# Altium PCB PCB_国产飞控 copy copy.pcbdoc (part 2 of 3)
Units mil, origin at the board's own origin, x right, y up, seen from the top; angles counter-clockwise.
Board outline 2782.5 x 2450 mil, 4 copper layers (Top Layer, Inner1, Inner2, Bottom Layer), stack 2.757 mil thick; 92 components, 104 nets, 474 pads, 149 vias.
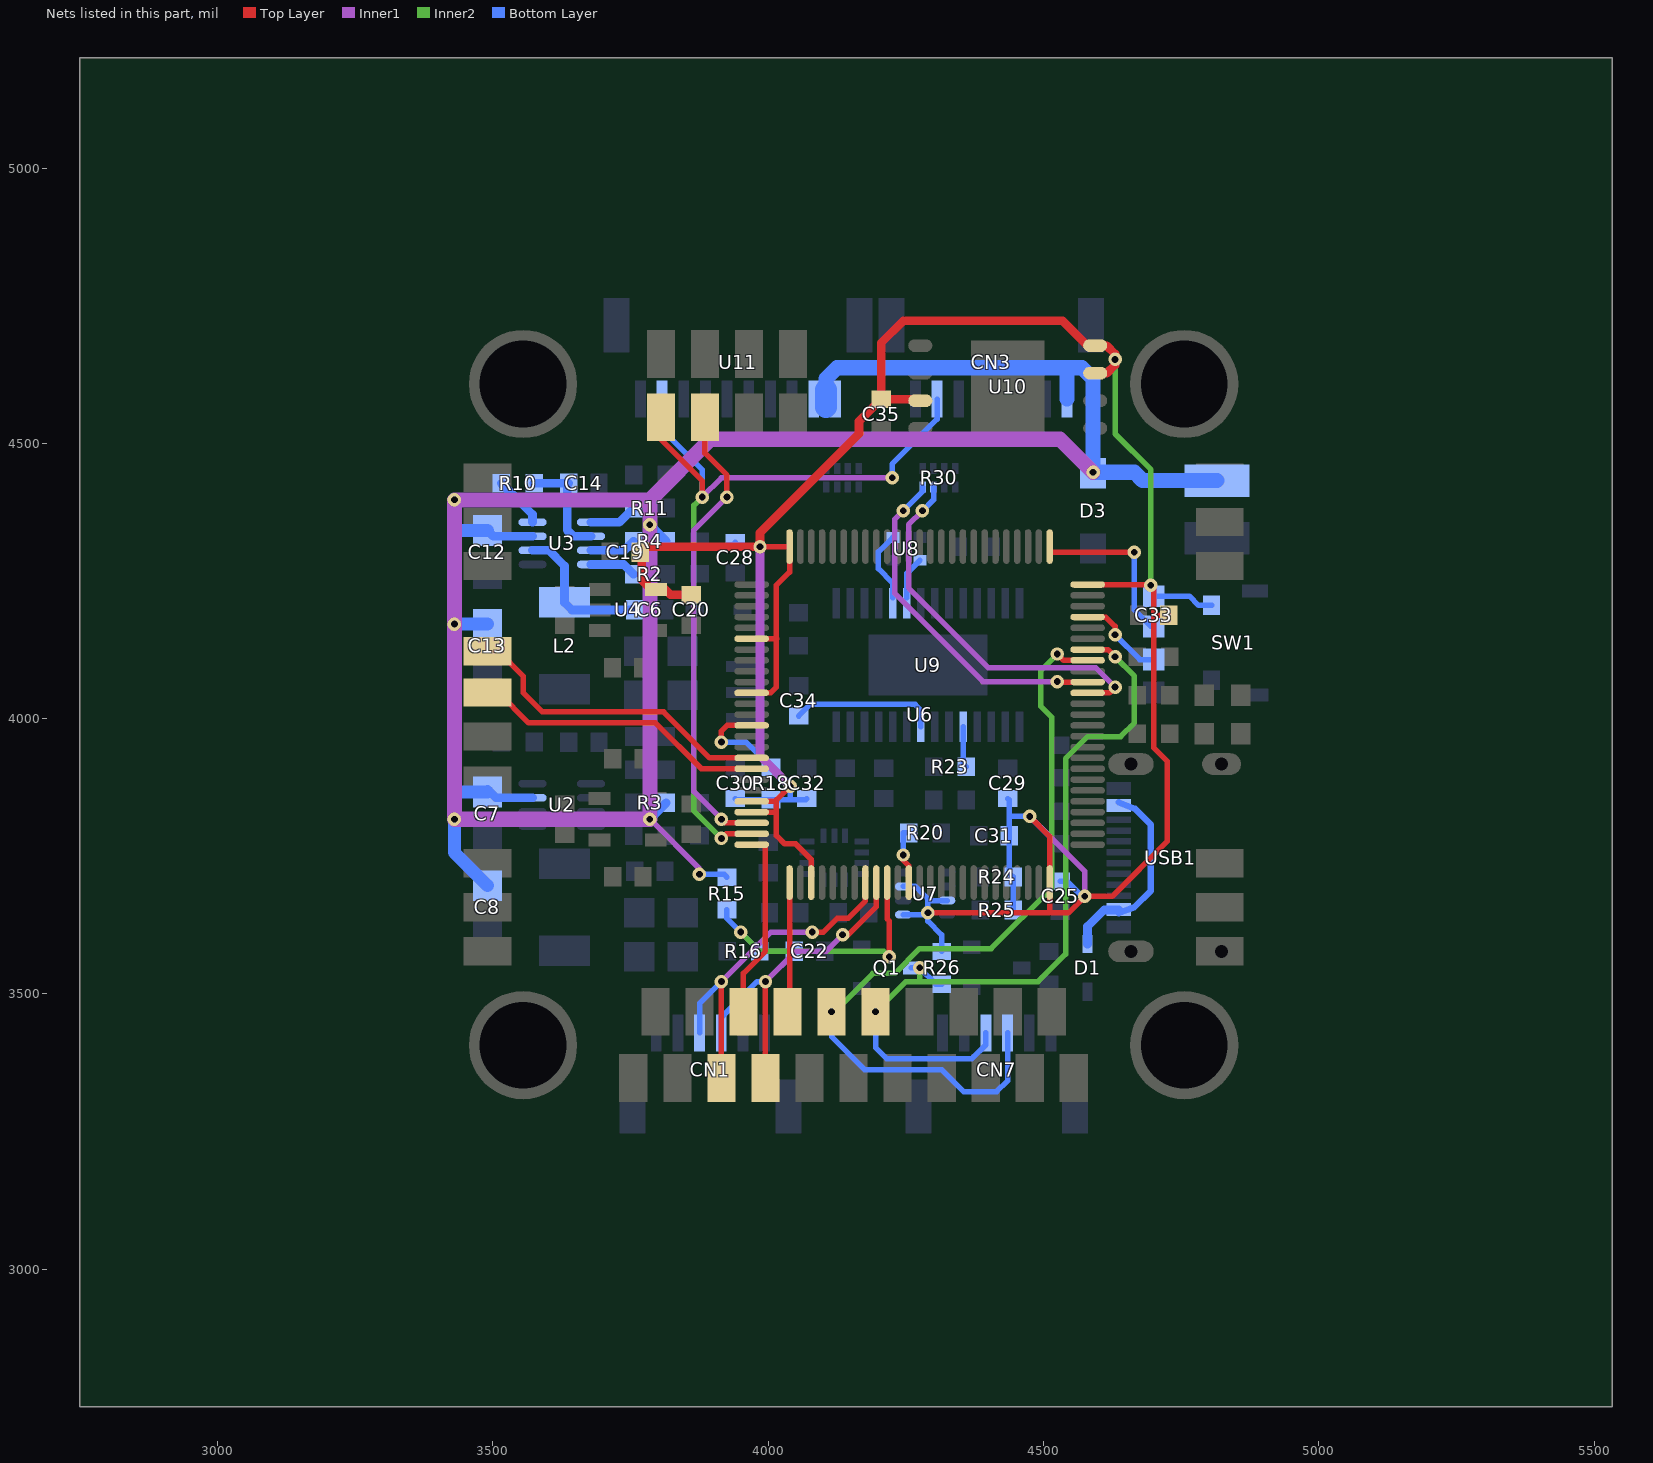
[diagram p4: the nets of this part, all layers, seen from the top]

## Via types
v1: diameter 24.41, hole 12.2, Top Layer to Bottom Layer, 149 vias

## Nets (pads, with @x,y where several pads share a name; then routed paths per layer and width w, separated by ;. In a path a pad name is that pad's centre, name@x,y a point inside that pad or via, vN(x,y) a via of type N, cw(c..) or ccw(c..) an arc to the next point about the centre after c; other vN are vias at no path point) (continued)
SERVO3: R30.2 U6.65 | length 705.8
  Top Layer w10: U6.65@4580.11,4046.87 4619.4,4046.9 v1(4630,4057.5)
  Inner1 w10: v1(4280,4377.5) 4255,4352.5 4255,4237.5 4400,4092.5 4595,4092.5 v1(4630,4057.5)
  Bottom Layer w10: v1(4280,4377.5) 4300.2,4397.7 R30.2@4300.16,4420.67
SERVO4: R30.1 U6.66 | length 630.9
  Top Layer w10: v1(4525,4067.5) 4525.9,4066.6 U6.66@4580.11,4066.56
  Inner1 w10: v1(4245,4377.5) 4230,4362.5 4230,4227.5 4390,4067.5 v1(4525,4067.5)
  Bottom Layer w10: v1(4245,4377.5) 4280.5,4413 R30.1@4280.47,4420.67
SWDCLK: pad.5@4700,4167.5 U6.76 | length 316.3
  Top Layer w10: U6.76@4511.22,4312.61 4511.2,4302.5 v1(4665,4302.5)
  Bottom Layer w10: v1(4665,4302.5) 4665,4197.5 4695,4167.5 pad.5@4700,4167.5
SWDIO: pad.5@4700,4107.5 U6.72 | length 160.7
  Top Layer w10: U6.72@4580.11,4184.67 4612.8,4184.7 4630,4167.5 v1(4630,4152.5)
  Bottom Layer w10: v1(4630,4152.5) 4675,4107.5 pad.5@4700,4107.5
U3_1: R11.1 U3.1 | length 87.8
  Bottom Layer w15.75: U3.1@3678.1,4356.9 3729.7,4356.9 R11.1@3755.34,4382.5
U3_2: C14.2 R10.1 U3.2 | length 196.4
  Bottom Layer w15.75: R10.1@3574.66,4427.5 C14.2@3637.45,4427.5 3635,4425.1 3635,4342.5 3646.2,4331.3 U3.2@3678.1,4331.3
U3_3: R4.1 U3.3 | length 84.2
  Bottom Layer w15.75: U3.3@3678.1,4305.7 3738.5,4305.7 R4.1@3755.34,4322.5
U3_4: R2.1 U3.4 | length 84.5
  Bottom Layer w15.75: U3.4@3678.1,4280.1 3737.7,4280.1 R2.1@3755.34,4262.5
U3_6: C6.2 L2.1 U3.6 | length 269.1
  Bottom Layer w15.75: U3.6@3572,4305.7 3601.8,4305.7 3630,4277.5 L2.1@3630,4211.24 3643.7,4197.5 C6.2@3757.45,4197.5
U3_8: R10.2 U3.8 | length 94
  Bottom Layer w15.75: R10.2@3515.34,4427.5 3571.9,4370.9 U3.8@3571.9,4356.9
U6_14: R18.1 U6.14 | length 187.9
  Top Layer w10: v1(3915,3957.5) 3915,3977.5 3925.3,3987.8 U6.14@3969.89,3987.81
  Bottom Layer w10: v1(3915,3957.5) 3959.7,3957.5 R18.1@4005,3912.16
U6_37: R20.2 U6.37 | length 104.7
  Top Layer w10: v1(4245,3752.5) 4245,3743.1 4255.3,3732.8 U6.37@4255.32,3702.39
  Bottom Layer w10: v1(4245,3752.5) 4245,3792.5 R20.2@4255.34,3792.5
U9_5: U8.1 U9.5 | length 131.2
  Bottom Layer w10: U9.5@4226,4219.7 4226,4246.5 4200,4272.5 4200,4302.8 U8.1@4226.4,4329.2
U9_6: U8.3 U9.6 | length 78
  Bottom Layer w10: U9.6@4251.6,4219.7 4251.6,4263.8 U8.3@4275.59,4287.82
U9_19: R23.1 U9.19 | length 75.2
  Bottom Layer w10: U9.19@4353.98,3985.29 4354,3918.2 R23.1@4359.66,3912.5
U9_22: C34.1 U9.22 | length 265.2
  Bottom Layer w10: C34.1@4055,4004.95 4075.9,4025.8 4266.7,4025.8 4277.2,4015.3 U9.22@4277.21,3985.29
UART1_RX: CN7.4 pad.5@4195,3467.5 Q1.3 R26.1 U6.69 | length 1483
  Top Layer w10: U6.69@4580.11,4125.61 4616.9,4125.6 v1(4630,4112.5)
  Inner2 w10: v1(4195,3467.5) 4250,3522.5 4490,3522.5 4540,3572.5 4540,3927.5 4580,3967.5 4640,3967.5 4665,3992.5 4665,4077.5 v1(4630,4112.5) ; 4275,3522.5 v1(4275,3547.5)
  Bottom Layer w10: v1(4195,3467.5) 4195,3402.5 4215,3382.5 4370,3382.5 4395.3,3407.8 CN7.4@4395.31,3429.43 ; Q1.3@4260.2,3547.5 v1(4275,3547.5) 4304.7,3517.8 R26.1@4315,3517.84
UART1_TX: CN7.3 pad.5@4115,3467.5 U6.68 | length 1500.3
  Top Layer w10: v1(4525,4117.5) 4536.6,4105.9 U6.68@4580.11,4105.93
  Inner2 w10: v1(4115,3467.5) 4120,3467.5 4190,3537.5 4230,3537.5 4275,3582.5 4405,3582.5 4515,3692.5 4515,4002.5 4495,4022.5 4495,4087.5 v1(4525,4117.5)
  Bottom Layer w10: v1(4115,3467.5) 4115,3422.5 4175,3362.5 4315,3362.5 4355,3322.5 4415,3322.5 4434.7,3342.2 CN7.3@4434.68,3429.43
UART2_RX: pad.5@4035,3467.5 U6.26 | length 238.7
  Top Layer w10: pad.5@4035,3467.5 4038.8,3467.5 U6.26@4038.78,3702.39
UART2_TX: pad.5@3955,3467.5 U6.25 | length 345.5
  Top Layer w10: pad.5@3955,3467.5 3955,3537.5 3995,3577.5 3995,3771.3 U6.25@3969.89,3771.28
UART3_RX: CN1.3 pad.5@3995,3347.5 U6.34 | length 611.5
  Top Layer w10: pad.5@3995,3347.5 3995,3407.5 v1(3995,3522.5) ; v1(4135,3607.5) 4145,3607.5 4196.3,3658.8 U6.34@4196.26,3702.39
  Inner1 w10: v1(3995,3522.5) 4050,3577.5 4105,3577.5 v1(4135,3607.5)
  Bottom Layer w10: CN1.3@3914.68,3429.43 3914.7,3457.2 3980,3522.5 v1(3995,3522.5)
UART3_TX: CN1.4 pad.5@3915,3347.5 U6.33 | length 640.2
  Top Layer w10: pad.5@3915,3347.5 3915,3412.5 v1(3915,3522.5) ; v1(4080,3612.5) 4100,3612.5 4125,3637.5 4145,3637.5 4176.6,3669.1 U6.33@4176.57,3702.39
  Inner1 w10: v1(3915,3522.5) 4005,3612.5 v1(4080,3612.5)
  Bottom Layer w10: CN1.4@3875.31,3429.43 3875.3,3482.8 v1(3915,3522.5)
UART4_RX: CN3.2 pad.5@3805,4547.5 U6.24 U11.2 | length 1626.1
  Top Layer w10: pad.5@3805,4547.5 3805,4507.5 3880,4432.5 v1(3880,4402.5) ; v1(3915,3782.5) 3923.5,3791 U6.24@3969.89,3790.96
  Inner1 w10: v1(3880,4402.5) 3915,4437.5 v1(4225,4437.5)
  Inner2 w10: v1(3880,4402.5) 3865,4387.5 3865,3832.5 v1(3915,3782.5)
  Bottom Layer w10: U11.2@3807.19,4580.57 3807.2,4525.3 3880,4452.5 v1(3880,4402.5) ; v1(4225,4437.5) 4225,4462.5 4306.6,4544.1 CN3.2@4306.59,4580.57
UART4_TX: pad.5@3885,4547.5 U6.23 | length 849.9
  Top Layer w10: pad.5@3885,4547.5 3885,4482.5 3925,4442.5 v1(3925,4402.5) ; v1(3915,3817.5) 3921.9,3810.6 U6.23@3969.89,3810.65
  Inner1 w10: v1(3915,3817.5) 3865,3867.5 3865,4342.5 v1(3925,4402.5)
UART8_RX: pad.5@3490,4047.5 U6.18 | length 537.2
  Top Layer w10: pad.5@3490,4047.5 3510,4047.5 3565,3992.5 3795,3992.5 3878.4,3909.1 U6.18@3969.89,3909.07
UART8_TX: pad.5@3490,4122.5 U6.17 | length 577.7
  Top Layer w10: pad.5@3490,4122.5 3510,4122.5 3555,4077.5 3555,4047.5 3590,4012.5 3810,4012.5 3893.7,3928.8 U6.17@3969.89,3928.76
VBAT: C7.2 C8.2 C12.2 C13.2 CN3.8 D3.1 pad.5@4815,4432.5 R3.2 R4.2 R15.2 U2.7 U3.7 U11.9 U11.10 | length 5122.4
  Inner1 w10: v1(3785,3817.5) 3875,3727.5 v1(3875,3717.5)
  Inner1 w27.56: v1(4590,4447.5) 4530,4507.5 3895,4507.5 3785,4397.5 ; 3785,4397.5 v1(3430,4397.5) v1(3430,3817.5) v1(3785,3817.5) v1(3785,4352.5) 3785,4397.5
  Bottom Layer w10: v1(3875,3717.5) 3919.7,3717.5 R15.2@3925,3712.16
  Bottom Layer w15.75: C7.2@3490,3871.9 3505.6,3856.3 U2.7@3572,3856.3 ; C12.2@3490,4341.87 3500.6,4331.3 U3.7@3572,4331.3 ; v1(3785,3817.5) R3.2@3814.66,3847.5 ; v1(3785,4352.5) R4.2@3814.66,4322.5
  Bottom Layer w23.62: v1(3430,4171.9) C13.2@3490,4171.87 ; v1(3430,4397.5) 3430,4341.9 ; 3435,3866.9 C7.2@3490,3866.87 ; C8.2@3490,3696.87 3430,3756.9 v1(3430,3817.5) 3430,4341.9 ; C12.2@3490,4341.87 3430,4341.9
  Bottom Layer w27.56: 4105,4580.6 4105,4617.5 4125,4637.5 4545,4637.5 4570,4637.5 4590,4617.5 v1(4590,4447.5) 4665,4447.5 4680,4432.5 pad.5@4815,4432.5 ; CN3.8@4542.81,4580.57 4542.8,4637.5
  Bottom Layer w39.37: 4105,4566.27 4105,4597.5
VBAT_ADC: C22.2 R15.1 R16.2 U6.35 | length 594.9
  Top Layer w10: U6.35@4215.94,3702.39 4215.9,3636.6 4220,3632.5 v1(4220,3567.5)
  Inner2 w10: v1(3950,3612.5) 3985,3577.5 4210,3577.5 v1(4220,3567.5)
  Bottom Layer w10: R15.1@3925,3652.84 3925,3637.2 R16.2@3984.66,3577.5 C22.2@4047.45,3577.5 ; v1(3950,3612.5) 3950,3612.2 v1@3954.7,3607.5
VBUS: D1.1 USB1.A4 USB1.A9 USB1.B4 USB1.B9 | length 366
  Bottom Layer w11.81: USB1.A9@4636.59,3647.11 4665,3657.5 4695,3687.5 4695,3807.5 4666.4,3836.1 USB1.A4@4636.59,3847.89
  Bottom Layer w15.75: D1.1@4580,3590.71 4580,3622.5 4610,3652.5 USB1.A9@4636.6,3652.5
VDD: C19.2 C20.2 C25.2 C28.2 C29.2 C30.2 C31.2 C32.2 C33.2 C35.1 pad.5@4700,4222.5 R18.2 R24.2 R25.2 R26.2 SW1.2 U4.5 U6.6 U6.11 U6.21 U6.22 U6.28 U6.50 U6.75 U6.100 U7.2 U7.6 U7.8 U10.3 U10.7 U10.8 | length 5390.1
  Top Layer w10: U6.22@3969.89,3830.33 4015,3830.3 ; U6.21@3969.89,3850.02 4012.5,3850 v1(4040,3877.5) ; U6.11@3969.89,4046.87 4004.4,4046.9 4015,4057.5 4015,4242.5 4038.8,4266.3 U6.100@4038.78,4312.61 3985.1,4312.6 v1(3985,4312.5) ; 4015,3852.5 4015,3830.3 ; U6.28@4078.1,3702.4 4078.1,3744.4 4050,3772.5 4030,3772.5 4015,3787.5 4015,3830.3 ; v1(4290,3647.5) 4545,3647.5 v1(4575,3677.5) 4625,3677.5 4725,3777.5 4725,3922.5 4700,3947.5 4700,4237.5 v1(4695,4242.5) 4695,4243.7 U6.75@4580.11,4243.72 ; v1(4475,3822.5) 4511.2,3786.3 U6.50@4511.22,3702.39 4511.2,3652.5 ; 4702.2,4187.5 C33.2@4727.56,4187.5
  Top Layer w10.08: U6.6@3969.89,4145.3 4015,4145.3
  Top Layer w15.75: C19.2@3767.86,4302.5 3767.9,4312.5 v1(3985,4312.5) 3985,4337.5 4165,4517.5 4165,4540.1 C35.1@4205,4580.06 ; C19.2@3770,4302.5 3770,4252.5 3787.6,4234.9 U4.5@3796.18,4234.9 3812.6,4234.9 3822.4,4225.1 C20.2@3850,4225.1 ; U10.3@4276.23,4577.5 4273.6,4580.1 C35.1@4205,4580.06 ; U10.7@4593.77,4627.5 4615,4627.5 4630,4642.5 v1(4630,4652.5) 4630,4662.5 4615,4677.5 U10.8@4593.77,4677.5 4580,4677.5 4535,4722.5 4245,4722.5 4205,4682.5 C35.1@4205,4580.06
  Inner1 w10: v1(4475,3822.5) 4575,3722.5 v1(4575,3677.5)
  Inner1 w15.75: v1(3985,4312.5) 3985,3932.5 v1(4040,3877.5)
  Inner2 w10: v1(4630,4652.5) 4630,4517.5 4695,4452.5 v1(4695,4242.5)
  Bottom Layer w10: C30.2@3940,3854.95 3942.1,3852.8 R18.2@4005,3852.84 4067.9,3852.8 C32.2@4070,3854.95 ; C28.2@3940,4320.06 3947.6,4312.5 v1(3985,4312.5) ; 4040,3852.84 v1(4040,3877.5) ; U7.8@4245.29,3644.11 4286.6,3644.1 v1(4290,3647.5) ; U7.6@4245.29,3695.3 4267.2,3695.3 4290,3672.5 v1(4290,3647.5) ; 4290,3669.7 U7.2@4324.7,3669.7 ; R26.2@4315,3577.16 4315,3607.5 4290,3632.5 v1(4290,3647.5) ; C29.2@4435,3854.95 4437.6,3852.4 C31.2@4437.56,3787.5 4437.6,3719.6 R24.2@4444.66,3712.5 R25.2@4444.66,3652.5 ; 4437.6,3822.6 4437.7,3822.5 v1(4475,3822.5) ; C25.2@4530,3705.05 4542.4,3705.1 4570,3677.5 v1(4575,3677.5) ; pad.5@4700,4222.5 4765,4222.5 4781.8,4205.7 SW1.2@4805.11,4205.68
pads on no net: CN3.1 SDO1.2 SDO1.3 SDO1.10 SDO1.11 SW1.3 SW1.4 U1.4 U4.4 U6.1 U6.2 U6.3 U6.4 U6.5 U6.7 U6.8 U6.9 U6.19 U6.38 U6.39 U6.40 U6.41 U6.42 U6.43 U6.44 U6.45 U6.46 U6.49 U6.51 U6.52 U6.53 U6.54 U6.55 U6.56 U6.57 U6.58 U6.59 U6.67 U6.73 U6.81 U6.83 U6.88 U6.89 U6.90 U6.91 U6.97 U6.98 U9.1 U9.2 U9.7 U9.12 U9.13 U9.14 U9.15 U9.16 U9.17 U9.18 U9.27 U9.28 U9.29 USB1.A5 USB1.A8 USB1.B5 USB1.B8

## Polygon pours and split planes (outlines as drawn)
GND on Inner2 (solid): 3025,4922.5 3025,3012.5 3020,3007.5 5150,3007.5 5150,4887.5 5095,4942.5
GND on Inner1 (solid): 3000,4945 3000,3050 3040,3010 5085,3010 5145,3070 5145,4920 5150,4925
GND on Top Layer (solid, pour order 4): 3030,4910 3030,3010 3040,3000 5110,3000 5130,3020 5130,4900 5125,4905
GND on Bottom Layer (solid, pour order 14): 3007.5,4935 3007.5,3040 3032.5,3015 5152.5,3015 5152.5,4915 5132.5,4935 5267.5,4935 5282.5,4950

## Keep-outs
Board Outline Layer:
  region: 4734.12,4628.38 4934.12,4828.38 cw(c4954.86,4807.36) 4975.88,4786.62 4775.88,4586.62 cw(c4755.14,4607.64)
  region: 4734.12,4628.38 4934.12,4828.38 cw(c4954.86,4807.36) 4975.88,4786.62 4775.88,4586.62 cw(c4755.14,4607.64)
  region: 4775.88,3428.38 4970.88,3233.38 cw(c4949.86,3212.64) 4929.12,3191.62 4734.12,3386.62 cw(c4755.14,3407.36)
  region: 4775.88,3428.38 4970.88,3233.38 cw(c4949.86,3212.64) 4929.12,3191.62 4734.12,3386.62 cw(c4755.14,3407.36)
  region: 3575.88,3386.62 3380.88,3191.62 cw(c3360.14,3212.64) 3339.12,3233.38 3534.12,3428.38 cw(c3554.86,3407.36)
  region: 3575.88,3386.62 3380.88,3191.62 cw(c3360.14,3212.64) 3339.12,3233.38 3534.12,3428.38 cw(c3554.86,3407.36)
  region: 3534.12,4586.62 3334.12,4786.62 cw(c3355.14,4807.36) 3375.88,4828.38 3575.88,4628.38 cw(c3554.86,4607.64)
  region: 3534.12,4586.62 3334.12,4786.62 cw(c3355.14,4807.36) 3375.88,4828.38 3575.88,4628.38 cw(c3554.86,4607.64)
  lines w0.1: 3334.12,4786.62 3534.12,4586.62 ccw(c3554.86,4607.64) 3575.88,4628.38 3375.88,4828.38 ccw(c3355.14,4807.36) 3334.12,4786.62 ; 3339.12,3233.38 ccw(c3360.14,3212.64) 3380.88,3191.62 3575.88,3386.62 ccw(c3554.86,3407.36) 3534.12,3428.38 3339.12,3233.38 ; 4734.12,3386.62 4929.12,3191.62 ccw(c4949.86,3212.64) 4970.88,3233.38 4775.88,3428.38 ccw(c4755.14,3407.36) 4734.12,3386.62 ; 4734.12,4628.38 4934.12,4828.38 cw(c4954.86,4807.36) 4975.88,4786.62 4775.88,4586.62 cw(c4755.14,4607.64) 4734.12,4628.38
  lines w10: 3397.13,3407.11 3397.13,4607.89 cw(c3554.61,4607.89) 3554.61,4765.37 4755.39,4765.37 cw(c4755.39,4607.89) 4912.87,4607.89 4912.87,3407.11 cw(c4755.39,3407.11) 4755.39,3249.63 3554.61,3249.63 cw(c3554.61,3407.11) 3397.13,3407.11

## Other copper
Top Layer:
  region net BOX_MOSI: 4604.29,4516.05 4583.25,4516.05 4588.8,4506.3 4598.8,4506.3
  region net BOX_SCK: 4583.26,4588.93 4583.24,4566.05 4568.25,4572.5 4568.25,4582.5
  region net VDD: 4609.36,4617.24 4599.22,4637.74 4621.78,4645.41 4629.15,4630.51
  region net VDD: 4576.97,4667.93 4590.77,4688.93 4568.98,4699.66 4558.89,4687.48
  region net VDD: 4609.36,4687.74 4599.23,4667.24 4621.79,4659.58 4629.15,4674.48
  region net VDD: 4266.97,4588.86 4264.44,4566.12 4241.36,4572.23 4243.11,4587.97
  region net BOX_MISO: 4286.76,4616.05 4286.75,4638.93 4301.75,4632.5 4301.76,4622.5
  region net BOX_CS: 4270.07,4666.05 4261.63,4688.18 4248.81,4668.38 4255.17,4660.6
  region net VDD: 3995.48,4139.39 3995.48,4151.21 4010.6,4150.34 4010.6,4140.26
  region net VDD: 3995.5,4040.96 3995.46,4052.78 4004.38,4051.9 4004.42,4041.9
  region net HEXT_IN: 3944.31,4033.09 3944.29,4021.27 3929.29,4022.2 3929.31,4032.2
  region net HEXT_OUT: 3944.3,4001.59 3944.3,4013.41 3929.3,4012.5 3929.3,4002.5
  region net U6_14: 3944.3,3981.9 3944.3,3993.72 3929.3,3992.8 3929.3,3982.8
  region net I2C_SCL: 3995.49,3974.04 3995.47,3962.22 4010.47,3963.1 4010.49,3973.1
  region net I2C_SDA: 3995.5,3954.35 3995.47,3942.53 4010.47,3943.4 4010.49,3953.4
  region net UART8_TX: 3944.31,3934.67 3944.28,3922.85 3929.29,3923.8 3929.31,3933.8
  region net UART8_RX: 3944.31,3914.98 3944.29,3903.16 3929.29,3904.1 3929.31,3914.1
  region net VDD: 3995.49,3855.93 3995.47,3844.11 4010.47,3845 4010.49,3855
  region net VDD: 3995.49,3836.24 3995.47,3824.42 4010.47,3825.3 4010.49,3835.3
  region net UART4_TX: 3944.32,3804.74 3944.28,3816.55 3929.28,3815.6 3929.32,3805.6
  region net UART4_RX: 3944.32,3796.86 3944.28,3785.05 3929.29,3786 3929.31,3796
  region net UART2_TX: 4000.86,3773.72 3982.5,3765.37 3990,3750.37 4000,3750.37
  region net UART2_RX: 4044.68,3676.81 4032.87,3676.79 4033.8,3661.79 4043.8,3661.81
  region net VDD: 4084.05,3728 4072.24,3727.96 4073.1,3742.96 4083.1,3743
  region net GYRO_CS1: 4103.74,3727.99 4091.92,3727.97 4092.8,3742.97 4102.8,3742.99
  region net GYRO_SCK: 4123.43,3727.99 4111.61,3727.97 4112.5,3742.97 4122.5,3742.99
  region net GYRO_MISO: 4143.11,3727.98 4131.29,3727.98 4132.2,3742.98 4142.2,3742.98
  region net GYRO_MOSI: 4162.8,3727.98 4150.98,3727.98 4151.9,3742.98 4161.9,3742.98
  region net UART3_TX: 4182.48,3676.82 4170.66,3676.78 4171.6,3669.08 4181.6,3669.12
  region net UART3_RX: 4202.17,3676.81 4190.35,3676.78 4191.3,3661.79 4201.3,3661.81
  region net VBAT_ADC: 4221.85,3676.78 4210.03,3676.81 4210.9,3661.81 4220.9,3661.79
  region net CURRENT1: 4241.54,3676.79 4229.72,3676.81 4230.6,3661.81 4240.6,3661.79
  region net LED: 4458.08,3727.96 4446.27,3728 4447.2,3735.32 4457.2,3735.28
  region net BEEPER: 4477.76,3727.96 4465.95,3728 4466.9,3743 4476.9,3742.96
  region net VDD: 4517.13,3727.99 4505.32,3727.97 4506.2,3742.97 4516.2,3742.99
  region net VDD: 4517.13,3676.79 4505.32,3676.81 4506.2,3661.81 4516.2,3661.79
  region net GYRO_EXTI2: 4554.54,3942.53 4554.5,3954.35 4540.89,3953.4 4540.92,3943.4
  region net LED1: 4605.71,3974.04 4605.69,3962.22 4620.69,3963.1 4620.71,3973.1
  region net LED2: 4605.7,3993.72 4605.7,3981.9 4620.7,3982.8 4620.7,3992.8
  region net SERVO1: 4605.7,4001.59 4605.7,4013.41 4620,4012.5 4620,4002.5
  region net SERVO2: 4554.53,4033.09 4554.51,4021.27 4539.51,4022.2 4539.53,4032.2
  region net SERVO3: 4605.71,4040.96 4605.69,4052.78 4619.39,4051.9 4619.41,4041.9
  region net SERVO4: 4554.53,4072.47 4554.5,4060.65 4539.51,4061.6 4539.53,4071.6
  region net UART1_TX: 4554.53,4100.02 4554.51,4111.84 4539.51,4110.9 4539.53,4100.9
  region net UART1_RX: 4605.71,4131.52 4605.7,4119.7 4616.9,4120.6 4616.9,4130.6
  region net D-: 4554.52,4139.39 4554.52,4151.21 4539.52,4150.3 4539.52,4140.3
  region net D+: 4554.53,4170.89 4554.51,4159.07 4539.51,4160 4539.53,4170
  region net SWDIO: 4605.73,4178.77 4605.68,4190.58 4612.78,4189.7 4612.82,4179.7
  region net VDD: 4605.71,4249.63 4605.69,4237.82 4620.69,4238.7 4620.71,4248.7
  region net SWDCLK: 4517.13,4315 4517.13,4290 4532.13,4297.5 4532.13,4307.5
  region net GYRO_EXTI1: 4497.45,4287 4485.64,4287.04 4486.5,4272.03 4496.5,4272.01
  region net BOX_SCK: 4477.76,4338.18 4465.95,4338.22 4466.9,4353.22 4476.9,4353.18
  region net BOX_MISO: 4458.08,4338.19 4446.26,4338.21 4447.2,4353.21 4457.2,4353.19
  region net BOX_MOSI: 4438.39,4338.19 4426.57,4338.21 4427.5,4353.21 4437.5,4353.19
  region net AT_SCK: 4399.02,4287.01 4387.2,4287.03 4388.1,4279.41 4398.1,4279.39
  region net AT_MISO: 4359.65,4286.99 4347.83,4287.05 4348.7,4278.82 4358.7,4278.78
  region net AT_MOSI: 4339.97,4287.03 4328.15,4287 4329.1,4272.01 4339.1,4272.03
  region net AT_CS: 4320.28,4287.04 4308.46,4287 4309.4,4276.88 4319.4,4276.91
  region net BOX_CS: 4300.6,4338.2 4288.78,4338.2 4289.7,4352.2 4299.7,4352.2
  region net MOTOR1: 4202.17,4338.18 4190.35,4338.22 4191.3,4351.22 4201.3,4351.19
  region net MOTOR2: 4182.48,4338.19 4170.66,4338.21 4171.6,4353.21 4181.6,4353.19
  region net BOOT0: 4162.8,4287.02 4150.98,4287.02 4151.86,4271.9 4161.94,4271.9
  region net MOTOR3: 4143.11,4338.2 4131.29,4338.2 4132.2,4353.2 4142.2,4353.2
  region net MOTOR4: 4123.43,4338.21 4111.61,4338.19 4112.5,4349.99 4122.5,4350.01
  region net VDD: 4044.68,4287.03 4032.87,4287.01 4033.8,4272.01 4043.8,4272.03
  region net VDD: 4032.87,4300.1 4032.87,4325.1 4017.87,4317.6 4017.87,4307.6
  region net VDD: 4219.46,4564.31 4187.28,4586.99 4178.23,4564.47 4191.3,4555.26
  region net VDD: 4187.28,4595.81 4222.72,4595.81 4212.87,4619.43 4197.13,4619.43
  region net VDD: 4222.72,4595.81 4222.72,4564.31 4246.34,4572.23 4246.34,4587.97
  region net VDD: 3783.61,4284.78 3752.12,4284.78 3762.13,4261.16 3777.87,4261.16
  region net R28_1: 4773.82,4030 4773.82,4055 4758.82,4047.5 4758.82,4037.5
  region net R27_1: 4773.82,3960 4773.82,3985 4758.82,3977.5 4758.82,3967.5
  region net R28_1: 4745.53,4030 4745.53,4055 4760.53,4047.5 4760.53,4037.5
  region net LED2: 4682.8,4025.49 4657.8,4025.49 4665.3,4022.8 4675.3,4022.8
  region net R27_1: 4745.53,3960 4745.53,3985 4760.53,3977.5 4760.53,3967.5
  region net LED1: 4654.47,3955.6 4654.47,3980.6 4639.47,3973.1 4639.47,3963.1
  region net VDD: 3842.59,4209.31 3842.59,4240.81 3822.4,4232.97 3822.4,4217.23
  region net +5V: 3756.51,4110.22 3788,4110.22 3759.8,4133.84 3737.53,4133.84
  region net +5V: 3788,4110.22 3788,4074.78 3811.62,4084.63 3811.62,4100.37
  region net +5V: 3648.02,4185.69 3646.46,4154.19 3646.83,4154.53 3652.93,4170.71
  region net 3V3-IMU: 3877.72,3844.96 3852.68,3829.31 3874.62,3822.13 3884.9,3828.55
  region net 3V3-IMU: 3788.31,3909.78 3756.81,3909.78 3764.73,3886.16 3780.47,3886.16
  region net +5V: 3733.19,3694.78 3701.69,3694.78 3707.13,3671.16 3722.87,3671.16
  region net +5V: 3701.69,3730.22 3733.19,3730.22 3725.37,3745 3709.63,3745
  region net +5V: 3612.28,3829.31 3612.28,3860.81 3588.66,3852.97 3588.66,3837.23
  region net +5V: 3646.73,3860.81 3647.72,3829.31 3652.74,3844.1 3646.83,3860.47
  region net +5V: 3713.5,4246.71 3713.5,4223.09 3717.6,4227.03 3717.6,4242.77
  region net +5V: 3674.13,4240.01 3712.93,4246.71 3675.6,4264.24 3656.6,4260.96
  region net +5V: 3713.5,4171.91 3713.5,4148.29 3722.6,4152.23 3722.6,4167.97
  region net +5V: 3674.13,4148.29 3674.13,4171.91 3652.4,4167.97 3652.4,4152.23
  region net +5V: 3713.5,4171.91 3713.5,4148.29 3722.4,4152.23 3722.4,4167.97
  region net VDD: 3776.5,4223.09 3802.51,4246.71 3777.62,4256.02 3765.95,4245.42
  region net VDD: 3815.87,4246.71 3810.73,4223.09 3816.83,4219.53 3824.39,4234.24
  region net +5V: 3713.2,3866.71 3713.2,3843.09 3722.6,3847.03 3722.6,3862.77
  region net +5V: 3673.83,3843.09 3673.83,3866.71 3652.4,3862.77 3652.4,3847.03
  region net +5V: 3673.83,3866.71 3713.19,3866.71 3701.38,3869 3685.63,3869
  region net +5V: 3713.2,3768.29 3674.53,3768.29 3706.36,3745 3723.07,3750.57
  region net +5V: 3713.2,3791.91 3713.2,3768.29 3717.6,3772.23 3717.6,3787.97
  region net 3V3-IMU: 3776.19,3843.09 3799.22,3866.71 3778.17,3874.07 3767.1,3862.86
  region net 3V3-IMU: 3815.56,3866.71 3815.56,3843.09 3839.19,3847.03 3839.19,3862.77
  region net VDD: 4711.81,4175 4711.81,4200 4702.2,4192.5 4702.2,4182.5
  region net BOOT0: 4745.53,4100 4745.53,4125 4760.53,4117.5 4760.53,4107.5
  region net +5V: 4542.05,3390.81 4580.59,3382.75 4580.57,3386.93 4565.79,3394.43
  region net +5V: 4566.38,3304.19 4529.41,3304.19 4519.43,3288.07 4536.14,3282.5
  region net +5V: 4776.69,4337.81 4776.69,4377.19 4753.07,4365.37 4753.07,4349.63
  region net LED: 4776.69,4265 4776.69,4290 4761.69,4282.5 4761.69,4272.5
  region net +5V: 3533.31,4377.19 3533.31,4337.81 3556.93,4349.63 3556.93,4365.37
  region net LED: 3533.31,4274.16 3521.92,4251.91 3535.3,4245.13 3540.09,4254.49
  region net +5V: 3499.66,3683.09 3533.31,3662.65 3543.02,3684.38 3529.17,3692.8
  region net LED: 3533.31,3763.09 3533.31,3738.31 3548.31,3758.74 3548.31,3772.88
  region net LED: 4807.5,3763.09 4832.5,3763.09 4825,3778.09 4815,3778.09
  region net +5V: 4776.69,3637.82 4776.69,3677.18 4760,3665.37 4760,3649.63
  region net +5V: 3533.31,3882.35 3499.66,3861.91 3529.17,3852.2 3543.02,3860.62
  region net UART8_RX: 3533.31,4044.16 3521.92,4021.91 3535.3,4015.13 3540.09,4024.49
  region net UART8_TX: 3533.31,4119.16 3521.92,4096.91 3535.3,4090.13 3540.09,4099.49
  region net UART4_RX: 3820.81,4504.19 3795.81,4504.19 3816.24,4489.19 3830.38,4489.19
  region net UART4_TX: 3897.5,4504.19 3872.5,4504.19 3880,4489.19 3890,4489.19
  region net +5V: 4025.32,4590.81 4064.68,4590.81 4052.87,4614.43 4037.13,4614.43
  region net +5V: 4064.68,4619.19 4025.32,4619.19 4037.13,4595.57 4052.87,4595.57
  region net +5V: 4019.41,4705.81 4054.68,4705.81 4042.87,4729.43 4027.13,4729.43
  region net OSD_IN_CAM: 3910.59,4642.03 3900.43,4619.19 3913.58,4611.85 3917.93,4621.64
  region net +10V: 3779.41,4619.19 3779.41,4652.19 3755.79,4640.37 3755.79,4624.63
  region net OSD_OUT_VTX: 3810.43,3510.81 3820.59,3487.97 3827.93,3508.36 3823.58,3518.15
  region net +5V: 3855.32,3510.81 3894.68,3510.81 3882.87,3534.43 3867.13,3534.43
  region net +5V: 3894.68,3424.19 3855.32,3424.19 3867.13,3400.57 3882.87,3400.57
  region net UART3_RX: 3982.5,3390.81 4007.5,3390.81 4000,3405.81 3990,3405.81
  region net UART3_TX: 3902.5,3390.81 3927.5,3390.81 3920,3405.81 3910,3405.81
  region net I2C_SDA: 4278.34,3510.81 4300.59,3499.42 4307.37,3512.8 4298.01,3517.59
  region net I2C_SCL: 4355.81,3510.81 4380.59,3510.81 4390.38,3525.81 4376.24,3525.81
  region net BB: 4462.5,3390.81 4487.5,3390.81 4480,3405.81 4470,3405.81
  region net +5V: 4540.59,3487.18 4540.59,3447.82 4564.21,3459.63 4564.21,3475.37
  region net +5V: 4334.69,3304.19 4295.31,3304.19 4307.13,3282.5 4322.87,3282.5
  region net SBUS: 4209.41,3379.42 4231.66,3390.81 4211.99,3397.59 4202.63,3392.8
  region net +5V: 4174.69,3304.19 4135.31,3304.19 4147.13,3282.5 4162.87,3282.5
  region net UART2_TX: 3942.5,3510.81 3967.5,3510.81 3960,3525.81 3950,3525.81
  region net UART2_RX: 4026.3,3510.81 4051.3,3510.81 4043.8,3525.81 4033.8,3525.81
  region net +10V: 3729.41,3390.81 3764.68,3390.81 3752.87,3414.43 3737.13,3414.43
  region net I2C_SDA: 4265.85,3475.57 4284.15,3475.57 4280,3484.12 4270,3484.12
  region net I2C_SCL: 4345.85,3475.57 4364.15,3475.57 4360,3484.12 4350,3484.12
  region net VDD: 4040.76,3865.32 4027.82,3878.26 4024.71,3869.29 4031.79,3862.21
  region net +5V: 3734.58,4160.86 3721.64,4147.92 3728.58,4142.78 3739.72,4153.92
  region net +5V: 3714.33,4150.95 3714.33,4169.25 3705.78,4167.97 3705.78,4152.23
  region net +5V: 3734.57,4159.23 3721.74,4172.29 3728.73,4177.36 3739.77,4166.13
  region net +5V: 3714.33,4150.95 3714.33,4169.25 3705.78,4167.97 3705.78,4152.23
  region net VDD: 4487.18,3823.26 4474.24,3810.32 4483.21,3807.21 4490.29,3814.29
  region net VDD: 4298.07,3638.35 4298.07,3656.65 4306.62,3652.5 4306.62,3642.5
  region net +5V: 3655.85,3909.43 3674.15,3909.43 3672.87,3900.88 3657.13,3900.88
  region net +5V: 4565.85,3459.43 4584.15,3459.43 4582.87,3450.88 4567.13,3450.88
  region net +5V: 4566.93,3458.35 4566.93,3476.65 4558.38,3475.37 4558.38,3459.63
  region net +5V: 4768.07,3648.35 4768.07,3666.65 4776.62,3665.37 4776.62,3649.63
  region net +5V: 4733.07,4348.35 4733.07,4366.65 4741.62,4365.37 4741.62,4349.63
  region net +5V: 4025.85,4724.43 4044.15,4724.43 4042.87,4715.88 4027.13,4715.88
  region net LED: 4768.07,4268.35 4768.07,4286.65 4776.62,4282.5 4776.62,4272.5
  region net LED: 3550.76,3755.32 3537.82,3768.26 3534.71,3759.29 3541.79,3752.21
  region net LED: 3550.76,4249.68 3537.82,4236.74 3534.71,4245.71 3541.79,4252.79
  region net LED: 4810.85,3789.43 4829.15,3789.43 4825,3780.88 4815,3780.88
  region net VDD: 4635.88,4663.2 4618.65,4656.99 4616.18,4665.18 4632.55,4671.08
  region net VDD: 4635.88,4641.8 4618.65,4648.01 4616.18,4639.82 4632.55,4633.92
  region net VDD: 4575.76,3665.32 4562.82,3678.26 4559.71,3669.29 4566.79,3662.21
  region net VDD: 4583.07,3668.35 4583.07,3686.65 4591.62,3682.5 4591.62,3672.5
  region net VDD: 3975.85,4320.57 3994.15,4320.57 3992.87,4329.12 3977.13,4329.12
  region net VDD: 3976.93,4303.35 3976.93,4321.65 3968.38,4320.37 3968.38,4304.63
  region net VDD: 3993.13,4303.4 3993.02,4321.7 4001.59,4317.6 4001.65,4307.6
  region net VDD: 4688.7,4232.05 4706.16,4237.56 4705,4228.23 4695,4225.08
  region net VDD: 4687.61,4252.21 4686.29,4233.95 4678.06,4238.7 4678.79,4248.7
  region net +10V: 3748.07,4623.35 3748.07,4641.65 3756.62,4640.37 3756.62,4624.63
  region net +5V: 3910.76,4125.32 3897.82,4138.26 3892.68,4131.32 3903.82,4120.18
  region net LED: 4418.07,3743.35 4418.07,3761.65 4426.62,3757.5 4426.62,3747.5
  region net SWDIO: 4620.85,4160.57 4639.15,4160.57 4635,4167.5 4625,4167.5
  region net SWDCLK: 4656.93,4293.35 4656.93,4311.65 4648.38,4307.5 4648.38,4297.5
  region net CURRENT1: 4260.76,3629.68 4247.82,3616.74 4244.71,3625.71 4251.79,3632.79
  region net VBAT_ADC: 4210.85,3575.57 4229.15,3575.57 4225,3584.12 4215,3584.12
  region net UART1_TX: 4537.18,4118.26 4524.24,4105.32 4533.06,4102.37 4540.13,4109.44
  region net UART1_RX: 4630.76,4124.68 4617.82,4111.74 4614.71,4120.71 4621.79,4127.79
  region net SERVO1: 4630.76,4005.32 4617.82,4018.26 4616.46,4011.04 4623.54,4003.96
  region net SERVO2: 4535.57,4038.6 4529.73,4021.25 4539.07,4022.2 4542.43,4032.2
  region net SERVO3: 4630.76,4045.32 4617.82,4058.26 4615.86,4050.43 4622.93,4043.36
  region net SERVO4: 4533.56,4076.2 4532.56,4057.92 4541.32,4061.6 4541.86,4071.6
  region net 3V3-IMU: 3961.93,3708.35 3961.93,3726.65 3953.38,3723.41 3953.38,3711.59
  region net UART4_RX: 3870.85,4410.57 3889.15,4410.57 3885,4419.12 3875,4419.12
  region net UART4_TX: 3915.85,4410.57 3934.15,4410.57 3930,4419.12 3920,4419.12
  region net UART4_RX: 3926.62,3778.76 3917.25,3794.5 3926.3,3796 3932.25,3786
  region net UART4_TX: 3926.14,3822.48 3918.54,3805.82 3927.83,3805.6 3932.4,3815.6
  region net OSD_IN_CAM: 3960.85,4410.57 3979.15,4410.57 3975,4419.12 3965,4419.12
  region net OSD_OUT_VTX: 3835.76,3510.32 3822.82,3523.26 3819.71,3514.29 3826.79,3507.21
  region net U6_14: 3905.85,3965.57 3924.15,3965.57 3920,3974.12 3910,3974.12
  region net HEXT_IN: 3885.85,4074.43 3904.15,4074.43 3900,4065.88 3890,4065.88
  region net HEXT_OUT: 3912.18,3996.74 3899.24,4009.68 3906.46,4011.04 3913.54,4003.96
  region net U6_37: 4239.43,3741.64 4256.47,3748.33 4256.15,3739.02 4245.99,3735.04
  region net UART3_TX: 4088.07,3603.35 4088.07,3621.65 4096.62,3617.5 4096.62,3607.5
  region net UART3_RX: 4145.7,3601.62 4139.49,3618.85 4148.76,3618.33 4152.51,3607.93
  region net BEEPER: 4480.02,3750.53 4461.83,3748.43 4466.9,3740.42 4476.9,3741.57
  region net I2C_SCL: 4405.76,3535.32 4392.82,3548.26 4389.71,3539.29 4396.79,3532.21
  region net I2C_SDA: 4341.93,3538.35 4341.93,3556.65 4335,3552.5 4335,3542.5
  region net I2C_SDA: 4275.85,3760.57 4294.15,3760.57 4290,3769.12 4280,3769.12
  region net I2C_SCL: 4335.85,3760.57 4354.15,3760.57 4350,3769.12 4340,3769.12
  region net UART3_RX: 3985.85,3514.43 4004.15,3514.43 4000,3505.88 3990,3505.88
  region net UART3_TX: 3905.85,3514.43 3924.15,3514.43 3920,3505.88 3910,3505.88
  region net +10V: 3735.85,3499.43 3754.15,3499.43 3752.87,3490.88 3737.13,3490.88
  region net SBUS: 4145.85,3539.43 4164.15,3539.43 4160,3530.88 4150,3530.88
  region net BB: 4465.85,3539.43 4484.15,3539.43 4480,3530.88 4470,3530.88
  region net D+: 4499.36,4175.34 4496.6,4157.24 4505.67,4160 4507.19,4170
  region net D-: 4473.07,4108.35 4473.07,4126.65 4481.62,4122.5 4481.62,4112.5
  region net GYRO_EXTI1: 4499.84,4264.71 4481.61,4266.37 4486.5,4274.5 4496.5,4273.6
  region net GYRO_EXTI2: 4487.18,3881.74 4474.24,3894.68 4483.21,3897.79 4490.29,3890.71
  region net GYRO_MISO: 4170.76,3790.32 4157.82,3803.26 4154.71,3794.29 4161.79,3787.21
  region net GYRO_CS1: 4066.66,3790.76 4082.06,3800.66 4083.29,3791.29 4074.68,3785.75
  region net GYRO_SCK: 4125.26,3815.9 4107.16,3813.14 4112.5,3805.31 4122.5,3806.83
  region net GYRO_MOSI: 4190.85,3809.43 4209.15,3809.43 4205,3800.88 4195,3800.88
  region net MOTOR1: 4200.85,4369.43 4219.15,4369.43 4215,4365 4205,4365
  region net MOTOR2: 4184.89,4370.35 4166.67,4368.58 4171.6,4360.48 4181.6,4361.44
  region net MOTOR3: 4147.66,4368 4129.62,4371.09 4132.2,4361.98 4142.2,4360.27
  region net MOTOR4: 4095.85,4369.43 4114.15,4369.43 4110,4362.5 4100,4362.5
  region net BOOT0: 4765.85,4120.57 4784.15,4120.57 4780.04,4129.12 4769.96,4129.12
  region net BOOT0: 4766.93,4103.35 4766.93,4121.65 4758.38,4117.5 4758.38,4107.5
  region net AT_MOSI: 4323.12,4267.58 4340.86,4263.07 4339.1,4272.33 4329.1,4274.88
  region net AT_MISO: 4378.15,4269.56 4368.26,4254.16 4363.25,4262.18 4368.79,4270.79
  region net AT_SCK: 4415.76,4269.68 4402.82,4256.74 4399.71,4265.71 4406.79,4272.79
  region net AT_CS: 4307.18,4256.74 4294.24,4269.68 4303.21,4272.79 4310.29,4265.71
  region net BOX_MOSI: 4508.07,4448.35 4508.07,4466.65 4516.62,4462.5 4516.62,4452.5
  region net BOX_MOSI: 4415.85,4449.43 4434.15,4449.43 4430,4440.88 4420,4440.88
Inner1:
  region net SERVO4: 4245.76,4365.32 4232.82,4378.26 4229.71,4369.29 4236.79,4362.21
  region net SERVO3: 4280.76,4365.32 4267.82,4378.26 4264.71,4369.29 4271.79,4362.21
  region net GYRO_EXTI2: 4052.18,3821.74 4039.24,3834.68 4048.21,3837.79 4055.29,3830.71
  region net GYRO_EXTI2: 4466.93,3873.35 4466.93,3891.65 4458.38,3887.5 4458.38,3877.5
  region net UART3_TX: 3927.18,3521.74 3914.24,3534.68 3923.21,3537.79 3930.29,3530.71
  region net UART3_RX: 4007.18,3521.74 3994.24,3534.68 4003.21,3537.79 4010.29,3530.71
  region net I2C_SCL: 4357.18,3753.26 4344.24,3740.32 4353.21,3737.21 4360.29,3744.29
  region net I2C_SDA: 4297.18,3753.26 4284.24,3740.32 4293.21,3737.21 4300.29,3744.29
  region net I2C_SDA: 4350.76,3559.68 4337.82,3546.74 4334.71,3555.71 4341.79,3562.79
  region net I2C_SCL: 4395.85,3555.57 4414.15,3555.57 4410,3564.12 4400,3564.12
  region net BEEPER: 4463.7,3747.05 4481.16,3752.56 4480,3743.23 4470,3740.08
  region net UART3_RX: 4135.76,3595.32 4122.82,3608.26 4119.71,3599.29 4126.79,3592.21
  region net UART3_TX: 4071.93,3603.35 4071.93,3621.65 4063.38,3617.5 4063.38,3607.5
  region net VBAT: 3797.18,3818.26 3784.24,3805.32 3793.21,3802.21 3800.29,3809.29
  region net VBAT: 3880.88,3728.2 3863.65,3721.99 3864.17,3731.26 3874.57,3735.01
  region net +5V: 4265.76,3914.68 4252.82,3901.74 4249.71,3910.71 4256.79,3917.79
  region net OSD_OUT_VTX: 3825.85,3530.57 3844.15,3530.57 3840,3539.12 3830,3539.12
  region net OSD_OUT_VTX: 4350.76,3805.32 4337.82,3818.26 4334.71,3809.29 4341.79,3802.21
  region net OSD_IN_CAM: 3982.18,4403.26 3969.24,4390.32 3978.21,4387.21 3985.29,4394.29
  region net UART4_TX: 3915.76,3829.68 3902.82,3816.74 3899.71,3825.71 3906.79,3832.79
  region net UART4_TX: 3925.76,4390.32 3912.82,4403.26 3909.71,4394.29 3916.79,4387.21
  region net UART4_RX: 3892.18,4401.74 3879.24,4414.68 3888.21,4417.79 3895.29,4410.71
  region net SERVO4: 4516.93,4058.35 4516.93,4076.65 4508.38,4072.5 4508.38,4062.5
  region net SERVO3: 4630.76,4069.68 4617.82,4056.74 4614.71,4065.71 4621.79,4072.79
  region net LED: 4422.18,3753.26 4409.24,3740.32 4418.21,3737.21 4425.29,3744.29
  region net UART4_RX: 4216.93,4428.35 4216.93,4446.65 4208.38,4442.5 4208.38,4432.5
  region net OSD_IN_CAM: 4055.76,4109.68 4042.82,4096.74 4039.71,4105.71 4046.79,4112.79
  region net VDD: 3975.85,4304.43 3994.15,4304.43 3992.87,4295.88 3977.13,4295.88
  region net VDD: 4565.85,3685.57 4584.15,3685.57 4580,3694.12 4570,3694.12
  region net LED: 4385.85,3360.57 4404.15,3360.57 4400,3369.12 4390,3369.12
  region net LED: 4385.85,3360.57 4404.15,3360.57 4400,3369.12 4390,3369.12
  region net LED: 4810.85,3789.43 4829.15,3789.43 4825,3780.88 4815,3780.88
  region net LED: 4810.85,3805.57 4829.15,3805.57 4825,3814.12 4815,3814.12
  region net LED: 3540.85,3759.43 3559.15,3759.43 3555,3750.88 3545,3750.88
  region net LED: 4772.18,4278.26 4759.24,4265.32 4768.21,4262.21 4775.29,4269.29
  region net +5V: 4112.18,4163.26 4099.24,4150.32 4108.21,4147.21 4115.29,4154.29
  region net +5V: 4715.85,4349.43 4734.15,4349.43 4732.87,4340.88 4717.13,4340.88
  region net +5V: 4715.85,4349.43 4734.15,4349.43 4730,4340.88 4720,4340.88
  region net +5V: 4760.76,3669.68 4747.82,3656.74 4742.68,3663.68 4753.82,3674.82
  region net VDD: 4487.18,3823.26 4474.24,3810.32 4483.21,3807.21 4490.29,3814.29
  region net +5V: 4533.24,4201.8 4520.3,4214.75 4529.28,4217.85 4536.35,4210.78
  region net VDD: 4040.76,3889.68 4027.82,3876.74 4022.68,3883.68 4033.82,3894.82
  region net BEEPER: 4465.85,3605.57 4484.15,3605.57 4480,3614.12 4470,3614.12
